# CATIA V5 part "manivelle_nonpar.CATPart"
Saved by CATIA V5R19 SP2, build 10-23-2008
Part number: manivelle
Bounding box of the stored display mesh (mm): x -7.954 to 42.5, y -30 to 45.75, z -7.954 to 7.954
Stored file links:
  F:\Projet CAO\pièces et assemblages\mécanisme 577\577-SaintAime\577-SaintAime\manivelle_nonpar.CATPart
  C:\Users\Tilou\Documents\Cours M1\Conception\conception fauroux\Projet CAO\pièces et assemblages\mécanisme 577\mecanisme 577.CATProduct
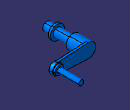
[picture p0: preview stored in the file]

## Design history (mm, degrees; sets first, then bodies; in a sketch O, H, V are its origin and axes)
Set1
  Plane1: type Offset, RefPlane yz-plane, Offset 36.5
  Plane2: type Offset, RefPlane face of Shaft1, Offset 1.25
  Point1: (36.5, 45.75, 3)
  Point2: (36.5, 45.75, -3)
  Point3: (36.5, 20.75, -3)
  Point4: (36.5, 20.75, 3)
  Line1: type PtPt, FirstPoint Point1, SecondPoint Point4
  Line2: type PtPt, FirstPoint Point2, SecondPoint Point3
Body1 (main body)
  Sketch1 on yz-plane, origin (0, 0, 0), H (0, 1, 0), V (0, 0, 1)
    point P1 (-30, 0)
    line L1 (-30, 0) -> (-30, 5)
    line L2 (-30, 5) -> (-20.5, 5)
    line L3 (-20.5, 5) -> (-20.5, 8)
    line L4 (-20.5, 8) -> (-18, 8)
    line L5 (-18, 8) -> (-18, 5)
    point P6 (-18, 5)
    line L6 (-18, 5) -> (0, 5)
    point P7 (0, 5)
    line L7 (0, 5) -> (0, 8)
    point P8 (0, 8)
    line L8 (0, 8) -> (18, 8)
    line L9 (18, 8) -> (18, 0)
    point P10 (18, 0)
    line L10 (18, 0) -> (-30, 0)
    distance L5 L7 = 18
    distance L3 L5 = 2.5
    distance L7 L9 = 18
    distance L6 L10 = 5
    distance L8 H = 8
    distance L1 L3 = 9.5
    coincidence: P1 H, P6 L2, P7 V, P8 L4, P10 H
    vertical: L1 V, L3 V, L5 V, L7 V, L9 V
    horizontal: L2 H, L4 H, L6 H, L8 H, L10 H
  Shaft1: profile Sketch1, axis Sketch1.L10, angle 360
  Loft1: solid, Sections (Sketch6; Sketch5)
  Sketch2 on Plane2, origin (0, 16.75, 0), H (1, 0, 0), V (0, 0, 1)
    circle A1 centre (36.5, 0) radius 6
    point P1 (36.5, 0)
    reference projected line E1 (36.5, 6) -> (36.5, -6) from edge [face of Loft1 | face of Loft1]
    radius A1 = 6
    coincidence: P1 H, P1 E1
  Pad1: profile Sketch2, direction (0, -1, 0), length 2, mirrored extent
  Sketch3 on start face of Pad1, origin (0, 18.75, 0), H (-1, 0, 0), V (0, 0, 1)
    circle A1 centre (-36.5, 0) radius 5
    point P1 (-36.5, 0)
    reference projected circle E1 centre (-36.5, 0) radius 6 from edge [start face of Pad1 | face of Pad1 from Sketch2.A1]
    radius A1 = 5
    coincidence: P1 H
    concentricity: A1 E1
  Pad2: profile Sketch3, direction (0, 1, 0), length 2
  Sketch4 on end face of Pad2, origin (0, 20.75, 0), H (-1, 0, 0), V (0, 0, 1)
    circle A1 centre (-36.5, 0) radius 3
    point P1 (-36.5, 0)
    reference projected circle E1 centre (-36.5, 0) radius 6 from edge [start face of Pad1 | face of Pad1 from Sketch2.A1]
    radius A1 = 3
    coincidence: P1 H
    concentricity: A1 E1
  Pad3: profile Sketch4, direction (0, 1, 0), length 25
  Sketch5 on Plane1, origin (36.5, 0, 0), H (0, 1, 0), V (0, 0, 1)
    line L1 (15.5, 6) -> (15.5, -6)
    line L2 (15.5, -6) -> (18, -6)
    line L3 (18, -6) -> (18, 6)
    line L4 (18, 6) -> (15.5, 6)
    reference projected line E1 (15.5, 8) -> (15.5, -8) from Sketch6.L2
    distance L3 L1 = 2.5
    distance L4 L2 = 12
    vertical: L1 V, L3 V
    horizontal: L2 H, L4 H
    symmetry: L4 L2 H
    coincidence: L1 E1
  Sketch6 on yz-plane, origin (0, 0, 0), H (0, 1, 0), V (0, 0, 1)
    projected line E1 (18, 8) -> (18, -8) from edge [face of Shaft1 from Sketch1.L8 | face of Shaft1 from Sketch1.L9]
    line L1 (18, 8) -> (15.5, 8)
    line L2 (15.5, 8) -> (15.5, -8)
    line L3 (15.5, -8) -> (18, -8)
    distance E1 L2 = 2.5
    horizontal: L1 H, L3 H
    vertical: L2 V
